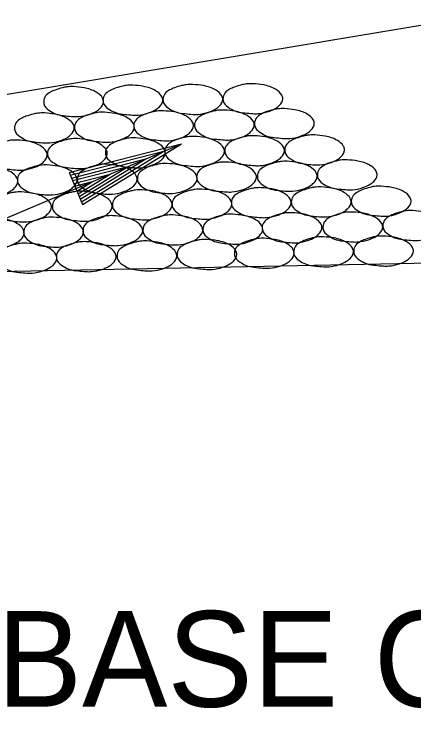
# Model space of a CAD drawing. Extents: x 60325 to 61047, y 53669 to 53767.
# Drawn here: x 60346.778 to 60348.864, y 53737.337 to 53741.105 of the extents above; entities that cross this region are included whole.
import ezdxf

# ---------------------------------------------------------------- set-up
doc = ezdxf.new("R2010")
doc.units = 0
doc.layers.add('R_Border Prem', color=7, linetype='Continuous')

msp = doc.modelspace()

# ---------------------------------------------------------------- linework, layer by layer
at = {"layer": 'R_Border Prem'}
for p, q in [((60349.2467, 53741.1045), (60340.428, 53739.6347)), ((60341.4044, 53737.789), (60347.6519, 53740.4285)), ((60347.0642, 53740.2779), (60347.6519, 53740.4285)), ((60347.1342, 53740.1121), (60347.6519, 53740.4285)), ((60347.07, 53740.2641), (60347.5596, 53740.3895)), ((60347.1284, 53740.1259), (60347.5596, 53740.3895)), ((60347.076, 53740.25), (60347.4646, 53740.3493)), ((60347.1225, 53740.14), (60347.4646, 53740.3493)), ((60347.0818, 53740.2362), (60347.3725, 53740.3104)), ((60347.1166, 53740.1538), (60347.3725, 53740.3104)), ((60347.0642, 53740.2779), (60347.1342, 53740.1121)), ((60347.0879, 53740.2218), (60347.2788, 53740.2709)), ((60347.1107, 53740.1679), (60347.2788, 53740.2709)), ((60347.0937, 53740.208), (60347.1865, 53740.2319)), ((60347.1047, 53740.182), (60347.1865, 53740.2319)), ((60355.2467, 53739.9311), (60340.428, 53739.6347))]:
    msp.add_line(p, q, dxfattribs=at)
for points in [[(60347.0875, 53740.7272), (60347.1425, 53740.721), (60347.2062, 53740.6985), (60347.2387, 53740.6672), (60347.2437, 53740.6485), (60347.2262, 53740.6147), (60347.2075, 53740.5997), (60347.1687, 53740.5822), (60347.115, 53740.571), (60347.0875, 53740.571), (60347.0462, 53740.5747), (60347.0012, 53740.5822), (60346.9675, 53740.5985), (60346.9362, 53740.6272), (60346.9312, 53740.6485), (60346.9412, 53740.6785), (60346.9662, 53740.6985), (60346.9912, 53740.7097), (60347.0287, 53740.721), (60347.0525, 53740.726), (60347.0875, 53740.7272)], [(60347.3971, 53740.7349), (60347.4521, 53740.7286), (60347.5158, 53740.7061), (60347.5483, 53740.6749), (60347.5533, 53740.6561), (60347.5358, 53740.6224), (60347.5171, 53740.6074), (60347.4783, 53740.5899), (60347.4246, 53740.5786), (60347.3971, 53740.5786), (60347.3558, 53740.5824), (60347.3108, 53740.5899), (60347.2771, 53740.6061), (60347.2458, 53740.6349), (60347.2408, 53740.6561), (60347.2508, 53740.6861), (60347.2758, 53740.7061), (60347.3008, 53740.7174), (60347.3383, 53740.7286), (60347.3621, 53740.7336), (60347.3971, 53740.7349)], [(60347.7105, 53740.7387), (60347.7655, 53740.7324), (60347.8293, 53740.7099), (60347.8618, 53740.6787), (60347.8668, 53740.6599), (60347.8493, 53740.6262), (60347.8305, 53740.6112), (60347.7918, 53740.5937), (60347.738, 53740.5824), (60347.7105, 53740.5824), (60347.6693, 53740.5862), (60347.6243, 53740.5937), (60347.5905, 53740.6099), (60347.5593, 53740.6387), (60347.5543, 53740.6599), (60347.5643, 53740.6899), (60347.5893, 53740.7099), (60347.6143, 53740.7212), (60347.6518, 53740.7324), (60347.6755, 53740.7374), (60347.7105, 53740.7387)], [(60348.024, 53740.7425), (60348.079, 53740.7363), (60348.1427, 53740.7138), (60348.1752, 53740.6825), (60348.1802, 53740.6638), (60348.1627, 53740.63), (60348.144, 53740.615), (60348.1052, 53740.5975), (60348.0515, 53740.5863), (60348.024, 53740.5863), (60347.9827, 53740.59), (60347.9377, 53740.5975), (60347.904, 53740.6138), (60347.8727, 53740.6425), (60347.8677, 53740.6638), (60347.8777, 53740.6938), (60347.9027, 53740.7138), (60347.9277, 53740.725), (60347.9652, 53740.7363), (60347.989, 53740.7413), (60348.024, 53740.7425)], [(60348.1888, 53740.6126), (60348.2438, 53740.6063), (60348.3075, 53740.5838), (60348.34, 53740.5526), (60348.345, 53740.5338), (60348.3275, 53740.5001), (60348.3088, 53740.4851), (60348.27, 53740.4676), (60348.2163, 53740.4563), (60348.1888, 53740.4563), (60348.1475, 53740.4601), (60348.1025, 53740.4676), (60348.0688, 53740.4838), (60348.0375, 53740.5126), (60348.0325, 53740.5338), (60348.0425, 53740.5638), (60348.0675, 53740.5838), (60348.0925, 53740.5951), (60348.13, 53740.6063), (60348.1538, 53740.6113), (60348.1888, 53740.6126)], [(60346.935, 53740.5897), (60346.99, 53740.5834), (60347.0538, 53740.5609), (60347.0863, 53740.5297), (60347.0913, 53740.5109), (60347.0738, 53740.4772), (60347.055, 53740.4622), (60347.0163, 53740.4447), (60346.9625, 53740.4334), (60346.935, 53740.4334), (60346.8938, 53740.4372), (60346.8488, 53740.4447), (60346.815, 53740.4609), (60346.7838, 53740.4897), (60346.7788, 53740.5109), (60346.7888, 53740.5409), (60346.8138, 53740.5609), (60346.8388, 53740.5722), (60346.8763, 53740.5834), (60346.9, 53740.5884), (60346.935, 53740.5897)], [(60347.2485, 53740.5935), (60347.3035, 53740.5872), (60347.3672, 53740.5647), (60347.3997, 53740.5335), (60347.4047, 53740.5147), (60347.3872, 53740.481), (60347.3685, 53740.466), (60347.3297, 53740.4485), (60347.276, 53740.4372), (60347.2485, 53740.4372), (60347.2072, 53740.441), (60347.1622, 53740.4485), (60347.1285, 53740.4647), (60347.0972, 53740.4935), (60347.0922, 53740.5147), (60347.1022, 53740.5447), (60347.1272, 53740.5647), (60347.1522, 53740.576), (60347.1897, 53740.5872), (60347.2135, 53740.5922), (60347.2485, 53740.5935)], [(60347.5581, 53740.6011), (60347.6131, 53740.5949), (60347.6768, 53740.5724), (60347.7093, 53740.5411), (60347.7143, 53740.5224), (60347.6968, 53740.4886), (60347.6781, 53740.4736), (60347.6393, 53740.4561), (60347.5856, 53740.4449), (60347.5581, 53740.4449), (60347.5168, 53740.4486), (60347.4718, 53740.4561), (60347.4381, 53740.4724), (60347.4068, 53740.5011), (60347.4018, 53740.5224), (60347.4118, 53740.5524), (60347.4368, 53740.5724), (60347.4618, 53740.5836), (60347.4993, 53740.5949), (60347.5231, 53740.5999), (60347.5581, 53740.6011)], [(60347.8753, 53740.6049), (60347.9303, 53740.5987), (60347.9941, 53740.5762), (60348.0266, 53740.5449), (60348.0316, 53740.5262), (60348.0141, 53740.4924), (60347.9953, 53740.4774), (60347.9566, 53740.4599), (60347.9028, 53740.4487), (60347.8753, 53740.4487), (60347.8341, 53740.4524), (60347.7891, 53740.4599), (60347.7553, 53740.4762), (60347.7241, 53740.5049), (60347.7191, 53740.5262), (60347.7291, 53740.5562), (60347.7541, 53740.5762), (60347.7791, 53740.5874), (60347.8166, 53740.5987), (60347.8403, 53740.6037), (60347.8753, 53740.6049)], [(60347.4104, 53740.4595), (60347.4654, 53740.4533), (60347.5291, 53740.4308), (60347.5616, 53740.3995), (60347.5666, 53740.3808), (60347.5491, 53740.347), (60347.5304, 53740.332), (60347.4916, 53740.3145), (60347.4379, 53740.3033), (60347.4104, 53740.3033), (60347.3691, 53740.307), (60347.3241, 53740.3145), (60347.2904, 53740.3308), (60347.2591, 53740.3595), (60347.2541, 53740.3808), (60347.2641, 53740.4108), (60347.2891, 53740.4308), (60347.3141, 53740.442), (60347.3516, 53740.4533), (60347.3754, 53740.4583), (60347.4104, 53740.4595)], [(60347.72, 53740.4672), (60347.775, 53740.4609), (60347.8387, 53740.4384), (60347.8712, 53740.4072), (60347.8762, 53740.3884), (60347.8587, 53740.3547), (60347.84, 53740.3397), (60347.8012, 53740.3222), (60347.7475, 53740.3109), (60347.72, 53740.3109), (60347.6787, 53740.3147), (60347.6337, 53740.3222), (60347.6, 53740.3384), (60347.5687, 53740.3672), (60347.5637, 53740.3884), (60347.5737, 53740.4184), (60347.5987, 53740.4384), (60347.6237, 53740.4497), (60347.6612, 53740.4609), (60347.685, 53740.4659), (60347.72, 53740.4672)], [(60348.0334, 53740.471), (60348.0884, 53740.4647), (60348.1522, 53740.4422), (60348.1847, 53740.411), (60348.1897, 53740.3922), (60348.1722, 53740.3585), (60348.1534, 53740.3435), (60348.1147, 53740.326), (60348.0609, 53740.3147), (60348.0334, 53740.3147), (60347.9922, 53740.3185), (60347.9472, 53740.326), (60347.9134, 53740.3422), (60347.8822, 53740.371), (60347.8772, 53740.3922), (60347.8872, 53740.4222), (60347.9122, 53740.4422), (60347.9372, 53740.4535), (60347.9747, 53740.4647), (60347.9984, 53740.4697), (60348.0334, 53740.471)], [(60348.3469, 53740.4748), (60348.4019, 53740.4686), (60348.4656, 53740.4461), (60348.4981, 53740.4148), (60348.5031, 53740.3961), (60348.4856, 53740.3623), (60348.4669, 53740.3473), (60348.4281, 53740.3298), (60348.3744, 53740.3186), (60348.3469, 53740.3186), (60348.3056, 53740.3223), (60348.2606, 53740.3298), (60348.2269, 53740.3461), (60348.1956, 53740.3748), (60348.1906, 53740.3961), (60348.2006, 53740.4261), (60348.2256, 53740.4461), (60348.2506, 53740.4573), (60348.2881, 53740.4686), (60348.3119, 53740.4736), (60348.3469, 53740.4748)], [(60346.7937, 53740.4481), (60346.8487, 53740.4418), (60346.9124, 53740.4193), (60346.9449, 53740.3881), (60346.9499, 53740.3693), (60346.9324, 53740.3356), (60346.9137, 53740.3206), (60346.8749, 53740.3031), (60346.8212, 53740.2918), (60346.7937, 53740.2918), (60346.7524, 53740.2956), (60346.7074, 53740.3031), (60346.6737, 53740.3193), (60346.6424, 53740.3481), (60346.6374, 53740.3693), (60346.6474, 53740.3993), (60346.6724, 53740.4193), (60346.6974, 53740.4306), (60346.7349, 53740.4418), (60346.7587, 53740.4468), (60346.7937, 53740.4481)], [(60347.1071, 53740.4557), (60347.1621, 53740.4495), (60347.2259, 53740.427), (60347.2584, 53740.3957), (60347.2634, 53740.377), (60347.2459, 53740.3432), (60347.2271, 53740.3282), (60347.1884, 53740.3107), (60347.1346, 53740.2995), (60347.1071, 53740.2995), (60347.0659, 53740.3032), (60347.0209, 53740.3107), (60346.9871, 53740.327), (60346.9559, 53740.3557), (60346.9509, 53740.377), (60346.9609, 53740.407), (60346.9859, 53740.427), (60347.0109, 53740.4382), (60347.0484, 53740.4495), (60347.0721, 53740.4545), (60347.1071, 53740.4557)], [(60346.6404, 53740.3105), (60346.6954, 53740.3042), (60346.7592, 53740.2817), (60346.7917, 53740.2505), (60346.7967, 53740.2317), (60346.7792, 53740.198), (60346.7604, 53740.183), (60346.7217, 53740.1655), (60346.6679, 53740.1542), (60346.6404, 53740.1542), (60346.5992, 53740.158), (60346.5542, 53740.1655), (60346.5204, 53740.1817), (60346.4892, 53740.2105), (60346.4842, 53740.2317), (60346.4942, 53740.2617), (60346.5192, 53740.2817), (60346.5442, 53740.293), (60346.5817, 53740.3042), (60346.6054, 53740.3092), (60346.6404, 53740.3105)], [(60346.95, 53740.3181), (60347.005, 53740.3119), (60347.0688, 53740.2894), (60347.1013, 53740.2581), (60347.1063, 53740.2394), (60347.0888, 53740.2056), (60347.07, 53740.1906), (60347.0313, 53740.1731), (60346.9775, 53740.1619), (60346.95, 53740.1619), (60346.9088, 53740.1656), (60346.8638, 53740.1731), (60346.83, 53740.1894), (60346.7988, 53740.2181), (60346.7938, 53740.2394), (60346.8038, 53740.2694), (60346.8288, 53740.2894), (60346.8538, 53740.3006), (60346.8913, 53740.3119), (60346.915, 53740.3169), (60346.95, 53740.3181)], [(60347.2635, 53740.322), (60347.3185, 53740.3157), (60347.3822, 53740.2932), (60347.4147, 53740.262), (60347.4197, 53740.2432), (60347.4022, 53740.2095), (60347.3835, 53740.1945), (60347.3447, 53740.177), (60347.291, 53740.1657), (60347.2635, 53740.1657), (60347.2222, 53740.1695), (60347.1772, 53740.177), (60347.1435, 53740.1932), (60347.1122, 53740.222), (60347.1072, 53740.2432), (60347.1172, 53740.2732), (60347.1422, 53740.2932), (60347.1672, 53740.3045), (60347.2047, 53740.3157), (60347.2285, 53740.3207), (60347.2635, 53740.322)], [(60347.5769, 53740.3258), (60347.6319, 53740.3195), (60347.6956, 53740.297), (60347.7281, 53740.2658), (60347.7331, 53740.247), (60347.7156, 53740.2133), (60347.6969, 53740.1983), (60347.6581, 53740.1808), (60347.6044, 53740.1695), (60347.5769, 53740.1695), (60347.5356, 53740.1733), (60347.4906, 53740.1808), (60347.4569, 53740.197), (60347.4256, 53740.2258), (60347.4206, 53740.247), (60347.4306, 53740.277), (60347.4556, 53740.297), (60347.4806, 53740.3083), (60347.5181, 53740.3195), (60347.5419, 53740.3245), (60347.5769, 53740.3258)], [(60347.8865, 53740.3334), (60347.9415, 53740.3272), (60348.0052, 53740.3047), (60348.0377, 53740.2734), (60348.0427, 53740.2547), (60348.0252, 53740.2209), (60348.0065, 53740.2059), (60347.9677, 53740.1884), (60347.914, 53740.1772), (60347.8865, 53740.1772), (60347.8452, 53740.1809), (60347.8002, 53740.1884), (60347.7665, 53740.2047), (60347.7352, 53740.2334), (60347.7302, 53740.2547), (60347.7402, 53740.2847), (60347.7652, 53740.3047), (60347.7902, 53740.3159), (60347.8277, 53740.3272), (60347.8515, 53740.3322), (60347.8865, 53740.3334)], [(60348.2038, 53740.3372), (60348.2588, 53740.331), (60348.3225, 53740.3085), (60348.355, 53740.2772), (60348.36, 53740.2585), (60348.3425, 53740.2247), (60348.3238, 53740.2097), (60348.285, 53740.1922), (60348.2313, 53740.181), (60348.2038, 53740.181), (60348.1625, 53740.1847), (60348.1175, 53740.1922), (60348.0838, 53740.2085), (60348.0525, 53740.2372), (60348.0475, 53740.2585), (60348.0575, 53740.2885), (60348.0825, 53740.3085), (60348.1075, 53740.3197), (60348.145, 53740.331), (60348.1688, 53740.336), (60348.2038, 53740.3372)], [(60348.5172, 53740.3449), (60348.5722, 53740.3386), (60348.6359, 53740.3161), (60348.6684, 53740.2849), (60348.6734, 53740.2661), (60348.6559, 53740.2324), (60348.6372, 53740.2174), (60348.5984, 53740.1999), (60348.5447, 53740.1886), (60348.5172, 53740.1886), (60348.4759, 53740.1924), (60348.4309, 53740.1999), (60348.3972, 53740.2161), (60348.3659, 53740.2449), (60348.3609, 53740.2661), (60348.3709, 53740.2961), (60348.3959, 53740.3161), (60348.4209, 53740.3274), (60348.4584, 53740.3386), (60348.4822, 53740.3436), (60348.5172, 53740.3449)], [(60348.0677, 53740.1995), (60348.1227, 53740.1932), (60348.1865, 53740.1707), (60348.219, 53740.1395), (60348.224, 53740.1207), (60348.2065, 53740.087), (60348.1877, 53740.072), (60348.149, 53740.0545), (60348.0952, 53740.0432), (60348.0677, 53740.0432), (60348.0265, 53740.047), (60347.9815, 53740.0545), (60347.9477, 53740.0707), (60347.9165, 53740.0995), (60347.9115, 53740.1207), (60347.9215, 53740.1507), (60347.9465, 53740.1707), (60347.9715, 53740.182), (60348.009, 53740.1932), (60348.0327, 53740.1982), (60348.0677, 53740.1995)], [(60348.3812, 53740.2033), (60348.4362, 53740.197), (60348.4999, 53740.1745), (60348.5324, 53740.1433), (60348.5374, 53740.1245), (60348.5199, 53740.0908), (60348.5012, 53740.0758), (60348.4624, 53740.0583), (60348.4087, 53740.047), (60348.3812, 53740.047), (60348.3399, 53740.0508), (60348.2949, 53740.0583), (60348.2612, 53740.0745), (60348.2299, 53740.1033), (60348.2249, 53740.1245), (60348.2349, 53740.1545), (60348.2599, 53740.1745), (60348.2849, 53740.1858), (60348.3224, 53740.197), (60348.3462, 53740.202), (60348.3812, 53740.2033)], [(60348.6946, 53740.2071), (60348.7496, 53740.2009), (60348.8133, 53740.1784), (60348.8458, 53740.1471), (60348.8508, 53740.1284), (60348.8333, 53740.0946), (60348.8146, 53740.0796), (60348.7758, 53740.0621), (60348.7221, 53740.0509), (60348.6946, 53740.0509), (60348.6533, 53740.0546), (60348.6083, 53740.0621), (60348.5746, 53740.0784), (60348.5433, 53740.1071), (60348.5383, 53740.1284), (60348.5483, 53740.1584), (60348.5733, 53740.1784), (60348.5983, 53740.1896), (60348.6358, 53740.2009), (60348.6596, 53740.2059), (60348.6946, 53740.2071)], [(60346.8155, 53740.177), (60346.8705, 53740.1707), (60346.9343, 53740.1482), (60346.9668, 53740.117), (60346.9718, 53740.0982), (60346.9543, 53740.0645), (60346.9355, 53740.0495), (60346.8968, 53740.032), (60346.843, 53740.0207), (60346.8155, 53740.0207), (60346.7743, 53740.0245), (60346.7293, 53740.032), (60346.6955, 53740.0482), (60346.6643, 53740.077), (60346.6593, 53740.0982), (60346.6693, 53740.1282), (60346.6943, 53740.1482), (60346.7193, 53740.1595), (60346.7568, 53740.1707), (60346.7805, 53740.1757), (60346.8155, 53740.177)], [(60347.1328, 53740.1808), (60347.1878, 53740.1745), (60347.2515, 53740.152), (60347.284, 53740.1208), (60347.289, 53740.102), (60347.2715, 53740.0683), (60347.2528, 53740.0533), (60347.214, 53740.0358), (60347.1603, 53740.0245), (60347.1328, 53740.0245), (60347.0915, 53740.0283), (60347.0465, 53740.0358), (60347.0128, 53740.052), (60346.9815, 53740.0808), (60346.9765, 53740.102), (60346.9865, 53740.132), (60347.0115, 53740.152), (60347.0365, 53740.1633), (60347.074, 53740.1745), (60347.0978, 53740.1795), (60347.1328, 53740.1808)], [(60347.4462, 53740.1884), (60347.5012, 53740.1822), (60347.565, 53740.1597), (60347.5975, 53740.1284), (60347.6025, 53740.1097), (60347.585, 53740.0759), (60347.5662, 53740.0609), (60347.5275, 53740.0434), (60347.4737, 53740.0322), (60347.4462, 53740.0322), (60347.405, 53740.0359), (60347.36, 53740.0434), (60347.3262, 53740.0597), (60347.295, 53740.0884), (60347.29, 53740.1097), (60347.3, 53740.1397), (60347.325, 53740.1597), (60347.35, 53740.1709), (60347.3875, 53740.1822), (60347.4112, 53740.1872), (60347.4462, 53740.1884)], [(60347.7581, 53740.1918), (60347.8131, 53740.1856), (60347.8769, 53740.1631), (60347.9094, 53740.1318), (60347.9144, 53740.1131), (60347.8969, 53740.0793), (60347.8781, 53740.0643), (60347.8394, 53740.0468), (60347.7856, 53740.0356), (60347.7581, 53740.0356), (60347.7169, 53740.0393), (60347.6719, 53740.0468), (60347.6381, 53740.0631), (60347.6069, 53740.0918), (60347.6019, 53740.1131), (60347.6119, 53740.1431), (60347.6369, 53740.1631), (60347.6619, 53740.1743), (60347.6994, 53740.1856), (60347.7231, 53740.1906), (60347.7581, 53740.1918)], [(60346.9826, 53740.0456), (60347.0376, 53740.0393), (60347.1014, 53740.0168), (60347.1339, 53739.9856), (60347.1389, 53739.9668), (60347.1214, 53739.9331), (60347.1026, 53739.9181), (60347.0639, 53739.9006), (60347.0101, 53739.8893), (60346.9826, 53739.8893), (60346.9414, 53739.8931), (60346.8964, 53739.9006), (60346.8626, 53739.9168), (60346.8314, 53739.9456), (60346.8264, 53739.9668), (60346.8364, 53739.9968), (60346.8614, 53740.0168), (60346.8864, 53740.0281), (60346.9239, 53740.0393), (60346.9476, 53740.0443), (60346.9826, 53740.0456)], [(60347.2922, 53740.0532), (60347.3472, 53740.0469), (60347.411, 53740.0244), (60347.4435, 53739.9932), (60347.4485, 53739.9744), (60347.431, 53739.9407), (60347.4122, 53739.9257), (60347.3735, 53739.9082), (60347.3197, 53739.8969), (60347.2922, 53739.8969), (60347.251, 53739.9007), (60347.206, 53739.9082), (60347.1722, 53739.9244), (60347.141, 53739.9532), (60347.136, 53739.9744), (60347.146, 53740.0044), (60347.171, 53740.0244), (60347.196, 53740.0357), (60347.2335, 53740.0469), (60347.2572, 53740.0519), (60347.2922, 53740.0532)], [(60347.6057, 53740.057), (60347.6607, 53740.0508), (60347.7244, 53740.0283), (60347.7569, 53739.997), (60347.7619, 53739.9783), (60347.7444, 53739.9445), (60347.7257, 53739.9295), (60347.6869, 53739.912), (60347.6332, 53739.9008), (60347.6057, 53739.9008), (60347.5644, 53739.9045), (60347.5194, 53739.912), (60347.4857, 53739.9283), (60347.4544, 53739.957), (60347.4494, 53739.9783), (60347.4594, 53740.0083), (60347.4844, 53740.0283), (60347.5094, 53740.0395), (60347.5469, 53740.0508), (60347.5707, 53740.0558), (60347.6057, 53740.057)], [(60347.9191, 53740.0608), (60347.9741, 53740.0546), (60348.0378, 53740.0321), (60348.0703, 53740.0008), (60348.0753, 53739.9821), (60348.0578, 53739.9483), (60348.0391, 53739.9333), (60348.0003, 53739.9158), (60347.9466, 53739.9046), (60347.9191, 53739.9046), (60347.8778, 53739.9083), (60347.8328, 53739.9158), (60347.7991, 53739.9321), (60347.7678, 53739.9608), (60347.7628, 53739.9821), (60347.7728, 53740.0121), (60347.7978, 53740.0321), (60347.8228, 53740.0433), (60347.8603, 53740.0546), (60347.8841, 53740.0596), (60347.9191, 53740.0608)], [(60348.2287, 53740.0685), (60348.2837, 53740.0622), (60348.3475, 53740.0397), (60348.38, 53740.0085), (60348.385, 53739.9897), (60348.3675, 53739.956), (60348.3487, 53739.941), (60348.31, 53739.9235), (60348.2562, 53739.9122), (60348.2287, 53739.9122), (60348.1875, 53739.916), (60348.1425, 53739.9235), (60348.1087, 53739.9397), (60348.0775, 53739.9685), (60348.0725, 53739.9897), (60348.0825, 53740.0197), (60348.1075, 53740.0397), (60348.1325, 53740.051), (60348.17, 53740.0622), (60348.1937, 53740.0672), (60348.2287, 53740.0685)], [(60348.546, 53740.0723), (60348.601, 53740.0661), (60348.6647, 53740.0436), (60348.6972, 53740.0123), (60348.7022, 53739.9936), (60348.6847, 53739.9598), (60348.666, 53739.9448), (60348.6272, 53739.9273), (60348.5735, 53739.9161), (60348.546, 53739.9161), (60348.5047, 53739.9198), (60348.4597, 53739.9273), (60348.426, 53739.9436), (60348.3947, 53739.9723), (60348.3897, 53739.9936), (60348.3997, 53740.0236), (60348.4247, 53740.0436), (60348.4497, 53740.0548), (60348.4872, 53740.0661), (60348.511, 53740.0711), (60348.546, 53740.0723)], [(60348.8594, 53740.08), (60348.9144, 53740.0737), (60348.9781, 53740.0512), (60349.0106, 53740.02), (60349.0156, 53740.0012), (60348.9981, 53739.9675), (60348.9794, 53739.9525), (60348.9406, 53739.935), (60348.8869, 53739.9237), (60348.8594, 53739.9237), (60348.8181, 53739.9275), (60348.7731, 53739.935), (60348.7394, 53739.9512), (60348.7081, 53739.98), (60348.7031, 53740.0012), (60348.7131, 53740.0312), (60348.7381, 53740.0512), (60348.7631, 53740.0625), (60348.8006, 53740.0737), (60348.8244, 53740.0787), (60348.8594, 53740.08)], [(60346.673, 53740.0415), (60346.728, 53740.0353), (60346.7918, 53740.0128), (60346.8243, 53739.9815), (60346.8293, 53739.9628), (60346.8118, 53739.929), (60346.793, 53739.914), (60346.7543, 53739.8965), (60346.7005, 53739.8853), (60346.673, 53739.8853), (60346.6318, 53739.889), (60346.5868, 53739.8965), (60346.553, 53739.9128), (60346.5218, 53739.9415), (60346.5168, 53739.9628), (60346.5268, 53739.9928), (60346.5518, 53740.0128), (60346.5768, 53740.024), (60346.6143, 53740.0353), (60346.638, 53740.0403), (60346.673, 53740.0415)], [(60348.0838, 53739.9352), (60348.1388, 53739.9289), (60348.2025, 53739.9064), (60348.235, 53739.8752), (60348.24, 53739.8564), (60348.2225, 53739.8227), (60348.2038, 53739.8077), (60348.165, 53739.7902), (60348.1113, 53739.7789), (60348.0838, 53739.7789), (60348.0425, 53739.7827), (60347.9975, 53739.7902), (60347.9638, 53739.8064), (60347.9325, 53739.8352), (60347.9275, 53739.8564), (60347.9375, 53739.8864), (60347.9625, 53739.9064), (60347.9875, 53739.9177), (60348.025, 53739.9289), (60348.0488, 53739.9339), (60348.0838, 53739.9352)], [(60348.3934, 53739.9428), (60348.4484, 53739.9366), (60348.5121, 53739.9141), (60348.5446, 53739.8828), (60348.5496, 53739.8641), (60348.5321, 53739.8303), (60348.5134, 53739.8153), (60348.4746, 53739.7978), (60348.4209, 53739.7866), (60348.3934, 53739.7866), (60348.3521, 53739.7903), (60348.3071, 53739.7978), (60348.2734, 53739.8141), (60348.2421, 53739.8428), (60348.2371, 53739.8641), (60348.2471, 53739.8941), (60348.2721, 53739.9141), (60348.2971, 53739.9253), (60348.3346, 53739.9366), (60348.3584, 53739.9416), (60348.3934, 53739.9428)], [(60348.7068, 53739.9466), (60348.7618, 53739.9404), (60348.8256, 53739.9179), (60348.8581, 53739.8866), (60348.8631, 53739.8679), (60348.8456, 53739.8341), (60348.8268, 53739.8191), (60348.7881, 53739.8016), (60348.7343, 53739.7904), (60348.7068, 53739.7904), (60348.6656, 53739.7941), (60348.6206, 53739.8016), (60348.5868, 53739.8179), (60348.5556, 53739.8466), (60348.5506, 53739.8679), (60348.5606, 53739.8979), (60348.5856, 53739.9179), (60348.6106, 53739.9291), (60348.6481, 53739.9404), (60348.6718, 53739.9454), (60348.7068, 53739.9466)], [(60346.8439, 53739.9097), (60346.8989, 53739.9035), (60346.9627, 53739.881), (60346.9952, 53739.8497), (60347.0002, 53739.831), (60346.9827, 53739.7972), (60346.9639, 53739.7822), (60346.9252, 53739.7647), (60346.8714, 53739.7535), (60346.8439, 53739.7535), (60346.8027, 53739.7572), (60346.7577, 53739.7647), (60346.7239, 53739.781), (60346.6927, 53739.8097), (60346.6877, 53739.831), (60346.6977, 53739.861), (60346.7227, 53739.881), (60346.7477, 53739.8922), (60346.7852, 53739.9035), (60346.8089, 53739.9085), (60346.8439, 53739.9097)], [(60347.1535, 53739.9174), (60347.2085, 53739.9111), (60347.2723, 53739.8886), (60347.3048, 53739.8574), (60347.3098, 53739.8386), (60347.2923, 53739.8049), (60347.2735, 53739.7899), (60347.2348, 53739.7724), (60347.181, 53739.7611), (60347.1535, 53739.7611), (60347.1123, 53739.7649), (60347.0673, 53739.7724), (60347.0335, 53739.7886), (60347.0023, 53739.8174), (60346.9973, 53739.8386), (60347.0073, 53739.8686), (60347.0323, 53739.8886), (60347.0573, 53739.8999), (60347.0948, 53739.9111), (60347.1185, 53739.9161), (60347.1535, 53739.9174)], [(60347.4708, 53739.9212), (60347.5258, 53739.915), (60347.5895, 53739.8925), (60347.622, 53739.8612), (60347.627, 53739.8425), (60347.6095, 53739.8087), (60347.5908, 53739.7937), (60347.552, 53739.7762), (60347.4983, 53739.765), (60347.4708, 53739.765), (60347.4295, 53739.7687), (60347.3845, 53739.7762), (60347.3508, 53739.7925), (60347.3195, 53739.8212), (60347.3145, 53739.8425), (60347.3245, 53739.8725), (60347.3495, 53739.8925), (60347.3745, 53739.9037), (60347.412, 53739.915), (60347.4358, 53739.92), (60347.4708, 53739.9212)], [(60347.7842, 53739.9289), (60347.8392, 53739.9226), (60347.903, 53739.9001), (60347.9355, 53739.8689), (60347.9405, 53739.8501), (60347.923, 53739.8164), (60347.9042, 53739.8014), (60347.8655, 53739.7839), (60347.8117, 53739.7726), (60347.7842, 53739.7726), (60347.743, 53739.7764), (60347.698, 53739.7839), (60347.6642, 53739.8001), (60347.633, 53739.8289), (60347.628, 53739.8501), (60347.638, 53739.8801), (60347.663, 53739.9001), (60347.688, 53739.9114), (60347.7255, 53739.9226), (60347.7492, 53739.9276), (60347.7842, 53739.9289)]]:
    msp.add_spline(points, degree=3, dxfattribs=at)

# ---------------------------------------------------------------- texts
msp.add_text('AGGREGATE BASE COURSE (CL. 7)', height=0.5, dxfattribs=at).set_placement((60342.2648, 53737.4878))

doc.saveas('drawing.dxf')
